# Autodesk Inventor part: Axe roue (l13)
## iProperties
Author: Flavien MARTY
Shininess: 60.0
PropertySet Name: _Private Model Information
Created: 2001-10
Part Number: Axe roue (l13)
Material: Par défaut
Document SubType Name: Modélisation
Designer: Flavien MARTY
Control State: 0
Master: False
Checked Out: False
PropertySet Name: Design Tracking Control
Density: 0.0
Volumn: 0.0
Area: 0.0
PropertySet Name: Model Information
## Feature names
1. Base1
